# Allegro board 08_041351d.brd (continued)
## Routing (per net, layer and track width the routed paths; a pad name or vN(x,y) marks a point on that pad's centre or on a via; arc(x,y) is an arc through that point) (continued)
IO_L11_SRCC_34_JX4_P: length 94.1
  TOP w0.089: U1.U14 v1(23.54,27.39)
  L12_SIGNAL w0.089: v1(84.38,32.75) 84.25,32.62 83.82,32.62 83.54,32.34 83.54,31.36 84.32,30.59 84.32,29.64 81.28,26.6 81.28,18.47 75.49,12.68 69.12,12.68 68.1,13.7 63.68,13.7 63.17,14.21 58.47,14.21 55.91,11.64 45.47,11.64 44.6,10.78 34.95,10.78 29.87,15.86 24.69,15.86 23.67,16.87 23.67,22.2 23.87,22.39 23.87,27.09 23.57,27.39 v1(23.54,27.39)
  BOTTOM w0.089: v1(84.38,32.75) 84.51,32.62 84.89,32.62 85.24,32.97 JX4.45
IO_L12_MRCC_13_JX2_N: length 53.6
  TOP w0.089: U1.U10 v1(23.54,31.39)
  L12_SIGNAL w0.089: v1(45.52,8.49) 45.26,8.24 45.26,7.47 44.4,6.61 34.7,6.61 30.61,10.7 29.59,10.7 28.88,11.41 28.88,12.5 28.45,12.94 22.28,12.94 21.64,13.57 21.64,14.59 19.99,16.24 19.99,31.2 20.27,31.48 20.75,31.48 20.75,31.48 21,31.72 23.2,31.72 v1(23.54,31.39)
  BOTTOM w0.089: JX2.38 45.53,7.34 45.26,7.6 45.26,8.24 v1(45.52,8.49)
IO_L12_MRCC_13_JX2_P: length 53.6
  TOP w0.089: U1.T9 v1(24.34,32.19)
  L12_SIGNAL w0.089: v1(24.34,32.19) 23.87,31.72 23.87,31.35 23.87,31.25 23.67,31.05 20.95,31.05 20.77,31.22 20.37,31.22 20.25,31.1 20.25,16.34 21.9,14.69 21.9,13.68 22.38,13.19 28.55,13.19 29.14,12.61 29.14,11.52 29.7,10.95 30.71,10.95 34.8,6.86 44.3,6.86 44.96,7.53 44.96,8.42 v1(44.88,8.49)
  BOTTOM w0.089: v1(44.88,8.49) 45.05,8.33 45.05,7.6 44.73,7.28 JX2.36
IO_L12_MRCC_34_JX4_N: length 96.1
  TOP w0.089: v1(23.54,23.39) U1.U19
  L6_SIGNAL w0.089: v1(82.97,32.24) 82.76,32.46 82.01,32.46 81.26,31.71 81.26,22.85 82.98,21.13 82.98,19.82 79.49,16.32 79.49,12.49 79.02,12.02 64.74,12.02 61.34,8.62 61.32,8.62 61.09,8.39 61.09,7.81 59.92,6.64 34.74,6.64 30.72,10.65 29.54,10.65 28.97,11.22 28.97,12.5 25.77,15.7 24.97,15.7 23.93,16.75 23.93,19.92 23.42,20.43 23.42,22.21 23.17,22.46 23.17,22.97 23.54,23.34 v1(23.54,23.39)
  BOTTOM w0.089: v1(82.97,32.24) 82.68,32.53 82.6,32.53 82.24,32.17 JX4.48
IO_L12_MRCC_34_JX4_P: length 96.2
  TOP w0.089: U1.U18 v1(23.54,24.19)
  L6_SIGNAL w0.089: v1(82.98,32.75) 82.98,32.75 82.97,32.75 82.93,32.71 81.9,32.71 81,31.81 81,22.75 82.73,21.02 82.73,19.92 79.24,16.43 79.24,12.6 78.92,12.28 64.63,12.28 61.23,8.87 61.22,8.87 60.84,8.5 60.84,7.92 59.81,6.89 34.84,6.89 30.83,10.9 29.65,10.9 29.23,11.33 29.23,12.61 25.88,15.96 25.08,15.96 24.18,16.85 24.18,20.03 23.67,20.53 23.67,22.21 23.87,22.4 23.87,23.53 23.54,23.86 v1(23.54,24.19)
  BOTTOM w0.089: JX4.46 82.38,32.97 82.6,32.75 v1(82.98,32.75)
IO_L12_MRCC_35_DATA_CLK_N: length 54.2
  TOP w0.127: U17.H11 v1(66.8,33.69) ; U1.K18 v1(29.94,24.19)
  L3_SIGNAL w0.095: v1(29.94,24.19) 29.52,23.77 29.52,22.33 30.96,20.89 40.73,20.89 41.66,19.97 57.7,19.97 v1(59.17,21.44)
  L6_SIGNAL w0.095: v1(66.8,33.69) 66.35,34.14 64.19,34.14 64.06,34.01 64.06,22.46 63.36,21.76 59.49,21.76 v1(59.17,21.44)
IO_L12_MRCC_35_DATA_CLK_P: length 51.1
  TOP w0.127: U1.K17 v1(29.94,24.99) ; U17.G11 v1(66,33.69)
  L7_SIGNAL w0.095: v1(58.73,24.87) 58.73,23.98 54.66,19.92 54.15,19.92 53.34,19.1 45.82,19.1 45.79,19.07 45.5,19.07 45.47,19.1 38.33,19.1 37.26,20.17 36.15,20.17 35.39,20.94 32.69,20.94 31.93,21.7 31.93,24.37 31.65,24.65 31.39,24.65 31.2,24.85 31.2,25.04 30.86,25.38 30.28,25.38 29.94,25.04 v1(29.94,24.99)
  L12_SIGNAL w0.095: v1(58.73,24.87) 59.11,25.25 61.27,25.25 61.66,25.65 61.66,25.83 61.86,26.03 62.04,26.03 62.46,26.45 62.46,26.63 62.66,26.83 62.84,26.83 63.26,27.25 63.26,27.43 63.46,27.63 63.64,27.63 64.06,28.05 64.06,28.23 64.26,28.43 64.44,28.43 64.82,28.81 64.82,30.97 65.2,31.35 65.2,33.26 65.64,33.69 v1(66,33.69)
IO_L13_35_TX_D0_N: length 46.7
  TOP w0.089: U1.H17 v1(31.54,24.99) ; U17.E12 v1(63.6,34.49)
  L7_SIGNAL w0.089: v1(31.54,24.99) 31.54,25.05 31.2,25.38 31.2,25.93 31.4,26.12 31.4,26.12 31.53,26.25 31.67,26.25 32,26.58 32,26.73 32.2,26.92 37.27,26.92 37.47,26.73 37.47,26.42 37.9,25.99 37.9,25.11 39.27,23.73 42.12,23.73 42.29,23.9 43.37,23.9 43.54,23.73 43.99,23.73 44.63,24.37 52.14,24.37 52.57,24.79 52.57,26.19 53.65,27.26 53.65,32.98 55.06,34.4 58.22,34.4 59.23,35.41 62.03,35.41 62.61,34.83 62.94,34.83 63.27,34.49 v1(63.6,34.49)
IO_L13_35_TX_D0_P: length 46.7
  TOP w0.089: U17.D11 v1(62.8,33.69) ; U1.H16 v1(31.54,25.79)
  L7_SIGNAL w0.089: v1(31.54,25.79) 31.69,25.64 31.8,25.64 31.93,25.76 31.93,26.15 32.03,26.25 32.56,26.25 32.71,26.4 32.82,26.4 32.96,26.25 33.31,26.25 33.45,26.4 33.56,26.4 33.71,26.25 34.07,26.25 34.22,26.4 34.33,26.4 34.47,26.25 34.87,26.25 35,26.38 35.23,26.38 35.36,26.25 35.74,26.25 35.74,26.27 35.87,26.4 35.98,26.4 36.12,26.25 36.48,26.25 36.63,26.4 36.74,26.4 36.88,26.25 37.28,26.25 37.64,25.89 37.64,25 39.17,23.48 42.04,23.48 42.29,23.23 43.37,23.23 43.61,23.48 44.1,23.48 44.73,24.11 52.25,24.11 52.82,24.68 52.82,26.08 53.9,27.16 53.9,32.87 55.17,34.14 58.32,34.14 59.34,35.16 61.92,35.16 62.46,34.62 62.46,34.35 62.67,34.15 62.93,34.15 63.02,34.24 63.36,34.24 63.43,34.18 63.43,34 63.19,33.76 62.87,33.76 v1(62.8,33.69)
IO_L13_MRCC_13_JX2_N: length 49.3
  TOP w0.089: U1.Y6 v1(21.14,34.59)
  L15_SIGNAL w0.089: v1(21.14,34.59) 21.41,34.32 21.6,34.32 21.79,34.12 22.07,34.12 22.4,33.8 22.4,33.5 22.58,33.32 22.87,33.32 23.07,33.13 23.07,32.69 23.23,32.52 23.67,32.52 23.93,32.27 23.93,31.92 24.06,31.79 24.4,31.79 24.67,31.53 24.67,31.16 24.8,31.03 28.44,31.03 28.94,30.52 28.94,21.19 30.09,20.05 30.09,18.59 30.44,18.23 30.44,15.04 34.08,11.41 44.14,11.41 45.09,12.36 45.09,13.1 45.56,13.57 46.61,13.57 47.13,13.06 v1(47.42,13.06)
  BOTTOM w0.089: v1(47.42,13.06) 47.42,12.61 47.64,12.39 47.64,12.05 47.93,11.76 JX2.43
IO_L13_MRCC_13_JX2_P: length 49.3
  TOP w0.089: U1.Y7 v1(21.14,33.79)
  L15_SIGNAL w0.089: v1(21.14,33.79) 21.41,34.06 21.5,34.06 21.6,33.96 21.6,33.65 21.8,33.45 22.08,33.45 22.4,33.13 22.4,32.85 22.6,32.65 22.75,32.65 23.07,32.33 23.07,32.02 23.29,31.79 23.7,31.79 23.99,31.5 23.99,31.25 24.27,30.98 24.49,30.98 24.49,30.98 24.69,30.78 28.33,30.78 28.69,30.42 28.69,21.09 29.83,19.94 29.83,18.48 30.19,18.13 30.19,14.94 33.97,11.16 44.25,11.16 45.34,12.25 45.34,13 45.66,13.32 46.5,13.32 46.71,13.11 46.71,12.94 46.54,12.68 46.54,12.55 46.66,12.43 46.79,12.43 v1(47.04,12.68)
  BOTTOM w0.089: v1(47.04,12.68) 47.42,12.3 47.42,12.05 47.13,11.75 JX2.41
IO_L13_MRCC_34_JX4_N: length 83.7
  TOP w0.089: U1.P19 v1(25.94,23.39)
  L13_SIGNAL w0.089: v1(88.52,29.82) 85.03,29.82 83.43,31.41 82.58,31.41 80.9,29.73 80.9,18.52 79.48,17.1 68.05,17.1 67.34,16.39 45.32,16.39 44.4,15.48 40.46,15.48 34.87,21.06 28.73,21.06 27.62,22.17 27.48,22.17 27.2,22.45 27.2,22.89 27.04,23.05 26.6,23.05 26.4,23.25 26.4,23.54 26.31,23.64 26.18,23.64 v1(25.94,23.39)
  BOTTOM w0.089: JX4.53 86.74,29.77 87.03,30.06 88.27,30.06 v1(88.52,29.82)
IO_L13_MRCC_34_JX4_P: length 83.6
  TOP w0.089: U1.N18 v1(26.74,24.19)
  L13_SIGNAL w0.089: v1(26.74,24.19) 26.49,23.94 26.49,23.82 26.58,23.72 26.87,23.72 27.2,23.4 27.2,23.25 27.4,23.05 27.56,23.05 27.87,22.74 27.87,22.28 28.83,21.32 34.98,21.32 40.57,15.73 44.3,15.73 45.21,16.64 67.24,16.64 67.95,17.36 79.38,17.36 80.65,18.62 80.65,29.84 82.48,31.67 83.53,31.67 85.13,30.07 88.06,30.07 v1(88.52,30.53)
  BOTTOM w0.089: JX4.51 86.73,30.57 87.03,30.28 88.27,30.28 v1(88.52,30.53)
IO_L14_35_TX_D1_N: length 41.2
  TOP w0.089: U17.E11 v1(63.6,33.69) ; U1.H18 v1(31.54,24.19)
  L3_SIGNAL w0.089: v1(31.54,24.19) 31.71,24.37 31.84,24.37 31.93,24.45 31.93,26.02 32.11,26.19 37.39,26.19 37.67,26.47 37.67,26.61 37.8,26.74 38.74,26.74 39.32,27.32 39.32,30.47 42.08,33.23 56.76,33.23 57.02,33.5 58.9,33.5 59.69,32.71 59.96,32.71 60.17,32.49 63.06,32.49 63.2,32.63 63.2,33.28 63.6,33.68 v1(63.6,33.69)
IO_L14_35_TX_D1_P: length 41.1
  TOP w0.089: U1.J18 v1(30.74,24.19) ; U17.D10 v1(62.8,32.89)
  L3_SIGNAL w0.089: v1(62.8,32.89) 62.8,33.19 62.69,33.29 60.3,33.29 59.97,32.96 59.79,32.96 59.01,33.75 56.92,33.75 56.65,33.48 41.97,33.48 39.07,30.58 39.07,27.43 38.63,26.99 31.34,26.99 31.14,26.79 31.14,24.6 v1(30.74,24.19)
IO_L14_SRCC_13_JX2_N: length 57.1
  TOP w0.089: U1.Y8 v1(21.14,32.99)
  L12_SIGNAL w0.089: v1(21.14,32.99) 20.01,32.99 19.74,32.71 19.74,31.96 19.23,31.46 19.23,15.73 20.12,14.84 20.12,13.85 22.02,11.94 22.02,11.28 22.7,10.6 28.67,10.6 33.73,5.54 45.75,5.54 47.55,7.35 v1(47.55,8.62)
  BOTTOM w0.089: JX2.44 47.93,7.31 47.64,7.6 47.64,8.07 47.45,8.26 47.45,8.52 v1(47.55,8.62)
IO_L14_SRCC_13_JX2_P: length 57
  TOP w0.089: U1.Y9 v1(21.14,32.19)
  L12_SIGNAL w0.089: v1(21.14,32.19) 20.83,32.49 20.83,32.65 20.74,32.73 20.12,32.73 19.99,32.61 19.99,31.86 19.48,31.35 19.48,15.83 20.37,14.95 20.37,13.95 22.28,12.05 22.28,11.39 22.81,10.86 28.78,10.86 33.84,5.8 45.64,5.8 47.3,7.45 47.3,7.6 47.17,7.73 46.92,7.73 46.79,7.86 46.79,7.98 46.92,8.11 47.17,8.11 47.3,8.24 47.3,8.4 47.21,8.48 47.21,8.48 47.21,8.49 47.17,8.49 v1(47.04,8.62)
  BOTTOM w0.089: JX2.42 47.13,7.31 47.42,7.6 47.42,7.98 47.23,8.17 47.23,8.43 v1(47.04,8.62)
IO_L14_SRCC_34_JX4_N: length 81.1
  TOP w0.089: U1.P20 v1(25.94,22.59)
  L13_SIGNAL w0.089: v1(25.94,22.59) 25.94,20.58 27.48,19.03 31.17,19.03 31.55,18.65 31.55,18.02 32.18,17.38 37.39,17.38 39.9,14.87 44.22,14.87 45.46,13.62 51.81,13.62 52.04,13.39 53.8,13.39 54.36,13.95 58.55,13.95 59.14,14.54 61.39,14.54 62.99,12.94 64.92,12.94 67.69,15.7 76.79,15.7 77.27,16.19 80.19,16.19 82.09,18.09 82.09,29.4 82.48,29.79 83.25,29.79 v1(83.74,30.28)
  BOTTOM w0.089: v1(83.74,30.28) 83.53,30.06 82.56,30.06 82.27,29.77 JX4.54
IO_L14_SRCC_34_JX4_P: length 81.1
  TOP w0.089: U1.N20 v1(26.74,22.59)
  L13_SIGNAL w0.089: v1(83.24,30.78) 83.24,30.49 83.32,30.4 83.32,30.22 83.15,30.04 82.37,30.04 81.84,29.51 81.84,18.19 80.09,16.44 77.17,16.44 76.68,15.96 67.59,15.96 64.82,13.19 63.1,13.19 61.49,14.79 59.03,14.79 58.45,14.21 54.25,14.21 53.69,13.65 52.15,13.65 51.92,13.88 45.57,13.88 44.32,15.12 40.01,15.12 37.5,17.63 32.29,17.63 31.8,18.12 31.8,18.76 31.27,19.29 27.59,19.29 26.19,20.69 26.19,22.23 26.28,22.32 26.47,22.32 v1(26.74,22.59)
  BOTTOM w0.089: JX4.52 82.29,30.57 82.58,30.28 83.29,30.28 83.42,30.41 83.42,30.6 v1(83.24,30.78)
IO_L15_13_JX2_N: length 57.3
  TOP w0.089: U1.W8 v1(21.94,32.99)
  L4_SIGNAL w0.089: v1(21.94,32.99) 21.52,32.57 20.87,32.57 20.73,32.43 20.73,32.18 20.6,32.05 20.09,32.05 19.36,31.32 19.36,20.83 21.16,19.03 25.52,19.03 26.79,17.76 36.78,17.76 38.94,15.6 41.7,15.6 42.47,14.84 42.47,8.49 43.23,7.73 47.86,7.73 48.48,8.35 49.88,8.35 50.22,8.68 v1(50.22,9.38)
  BOTTOM w0.089: v1(50.22,9.38) 50.09,9.51 50.09,9.95 50.33,10.19 JX2.49
IO_L15_13_JX2_P: length 57.3
  TOP w0.089: U1.V8 v1(22.74,32.99)
  L4_SIGNAL w0.089: v1(49.71,9.38) 49.96,9.13 49.96,8.79 49.78,8.6 48.38,8.6 47.75,7.98 43.34,7.98 42.72,8.6 42.72,14.94 41.81,15.86 39.04,15.86 36.88,18.02 26.89,18.02 25.62,19.29 21.26,19.29 19.61,20.94 19.61,31.21 20.19,31.79 22.07,31.79 22.34,32.07 22.34,32.59 v1(22.74,32.99)
  BOTTOM w0.089: JX2.47 49.53,10.26 49.87,9.91 49.87,9.54 v1(49.71,9.38)
IO_L15_34_JX4_N: length 87.5
  TOP w0.089: U1.U20 v1(23.54,22.59)
  L7_SIGNAL w0.089: v1(23.54,22.59) 23.54,16.5 24.18,15.86 26.49,15.86 27.38,14.97 31.24,14.97 32.63,13.57 33.58,13.57 34.47,12.68 34.47,11.92 35.49,10.9 40.44,10.9 40.95,11.41 65.94,11.41 71.28,16.75 73.59,16.75 74.28,17.44 74.28,22.29 74.71,22.71 78.03,22.71 80.32,25 85.47,25 v1(88.61,28.14)
  BOTTOM w0.089: JX4.59 86.74,27.37 87.03,27.66 88.14,27.66 v1(88.61,28.14)
IO_L15_34_JX4_P: length 87.5
  TOP w0.089: U1.T20 v1(24.34,22.59)
  L7_SIGNAL w0.089: v1(24.34,22.59) 24.16,22.41 23.92,22.41 23.79,22.28 23.79,16.61 24.29,16.11 26.6,16.11 27.48,15.22 31.34,15.22 32.74,13.82 33.69,13.82 34.72,12.79 34.72,12.02 35.59,11.16 40.33,11.16 40.84,11.67 65.84,11.67 71.17,17 73.48,17 74.03,17.55 74.03,22.4 74.6,22.97 77.92,22.97 80.21,25.25 85.37,25.25 88.13,28.01 v1(88.13,28.62)
  BOTTOM w0.089: JX4.57 86.75,28.17 87.04,27.88 88.05,27.88 88.23,28.06 88.23,28.24 88.13,28.34 v1(88.13,28.62)
IO_L15_35_TX_D2_N: length 54.5
  TOP w0.089: v1(33.14,22.59) U1.F20 ; U17.E10 v1(63.6,32.89)
  L6_SIGNAL w0.089: v1(33.14,22.59) 32.95,22.4 32.95,21.96 32.68,21.69 32.68,20.53 33.26,19.95 33.26,18.27 33.77,17.76 35.61,17.76 37.01,16.36 39.91,16.36 40.92,15.35 41.37,15.35 42.26,14.46 50.6,14.46 52.19,16.05 52.19,22.71 57.8,28.33 57.8,33.32 58.49,34.02 59.85,34.02 59.86,34.03 62.14,34.03 62.33,33.83 62.33,33.55 62.66,33.23 62.94,33.23 63.13,33.03 63.13,32.75 63.09,32.71 63.09,32.58 63.17,32.49 63.68,32.49 63.81,32.62 63.81,32.68 v1(63.6,32.89)
IO_L15_35_TX_D2_P: length 54.4
  TOP w0.089: U17.D9 v1(62.8,32.09) ; v1(33.14,23.39) U1.F19
  L6_SIGNAL w0.089: v1(33.14,23.39) 32.69,22.94 32.69,22.07 32.42,21.8 32.42,20.42 33.01,19.84 33.01,18.17 33.67,17.51 35.51,17.51 36.9,16.11 39.8,16.11 40.82,15.09 41.26,15.09 42.15,14.21 50.7,14.21 52.44,15.94 52.44,22.61 58.05,28.22 58.05,33.22 58.6,33.76 59.85,33.76 60.26,33.36 62.17,33.36 62.44,33.09 62.44,32.77 62.66,32.56 62.72,32.56 62.91,32.37 62.91,32.21 v1(62.8,32.09)
IO_L16_13_JX2_N: length 49.7
  TOP w0.089: U1.W9 v1(21.94,32.19)
  L15_SIGNAL w0.089: v1(21.94,32.19) 22.3,31.82 22.3,31.21 22.51,31.01 23.79,31.01 24.4,30.4 27.42,30.4 27.93,29.89 27.93,22.27 27.67,22.02 27.67,21.63 28.06,21.25 28.06,20.49 28.69,19.86 28.69,17.89 29.2,17.38 29.2,14.59 29.9,13.89 30.38,13.89 33.62,10.65 48.29,10.65 49.33,9.61 49.33,9.12 49.96,8.48 49.96,8.24 v1(50.22,7.98)
  BOTTOM w0.089: v1(50.22,7.98) 50.09,7.86 50.09,7.6 50.33,7.36 JX2.50
IO_L16_13_JX2_P: length 49.8
  TOP w0.089: U1.W10 v1(21.94,31.39)
  L15_SIGNAL w0.089: v1(49.71,7.98) 49.71,8.38 49.07,9.01 49.07,9.51 48.19,10.4 33.52,10.4 30.28,13.63 29.79,13.63 28.94,14.48 28.94,17.28 28.44,17.78 28.44,19.75 27.8,20.39 27.8,21.15 27.42,21.53 27.42,22.02 27.17,22.27 27.17,30.02 27.04,30.14 24.29,30.14 23.68,30.75 22.05,30.75 21.52,31.29 21.52,31.68 21.63,31.79 21.82,31.79 21.94,31.68 v1(21.94,31.39)
  BOTTOM w0.089: JX2.48 49.53,7.29 49.84,7.6 49.84,7.86 v1(49.71,7.98)
IO_L16_34_JX4_N: length 90
  TOP w0.089: v1(21.94,22.59) U1.W20
  L7_SIGNAL w0.089: v1(21.94,22.59) 21.94,16.07 23.04,14.97 26.21,14.97 27.23,13.95 31.17,13.95 35.1,10.01 40.82,10.01 41.52,10.71 66.39,10.71 68.28,12.61 76.47,12.61 77.63,13.76 80.71,13.76 81.97,15.02 81.97,18.68 81.39,19.26 79.05,19.26 78.6,19.71 78.6,20.67 78.87,20.93 v1(78.87,22.18)
  BOTTOM w0.089: v1(78.87,22.18) 78.64,22.41 78.64,27.16 79.14,27.66 80.48,27.66 80.78,27.37 JX4.60
IO_L16_34_JX4_P: length 90
  TOP w0.089: U1.V20 v1(22.74,22.59)
  L7_SIGNAL w0.089: v1(22.74,22.59) 22.19,22.04 22.19,16.18 23.14,15.22 26.32,15.22 27.34,14.21 31.27,14.21 35.21,10.27 40.71,10.27 41.41,10.97 66.28,10.97 68.18,12.86 76.37,12.86 77.52,14.01 80.6,14.01 81.71,15.12 81.71,18.57 81.28,19.01 78.94,19.01 78.35,19.6 78.35,20.77 78.61,21.04 78.61,21.88 78.51,21.98 78.39,21.98 v1(78.18,22.18)
  BOTTOM w0.089: v1(78.18,22.18) 78.42,22.42 78.42,27.25 79.05,27.88 80.46,27.88 80.76,28.17 JX4.58
IO_L16_35_TX_D3_N: length 52.9
  TOP w0.089: U17.E9 v1(63.6,32.09) ; U1.G18 v1(32.34,24.19)
  L12_SIGNAL w0.089: v1(32.34,24.19) 32.36,24.19 32.69,23.86 32.69,22.46 32.44,22.21 32.44,22.06 33.05,21.44 34.85,21.44 35.7,20.6 35.71,20.59 35.73,20.56 35.74,20.56 37,19.3 37.01,19.29 37.04,19.26 37.06,19.24 38.91,17.38 39.65,17.38 40.67,16.36 43.99,16.36 44.76,17.13 49.4,17.13 50.22,17.94 50.22,24.72 51.89,26.4 56.06,26.4 57.84,28.18 57.84,33.26 58.35,33.76 59.99,33.76 60.26,34.03 61.34,34.03 61.66,33.7 61.66,33.55 61.98,33.23 62.14,33.23 62.46,32.9 62.46,32.75 62.79,32.43 62.94,32.43 62.96,32.41 63.09,32.28 63.13,32.23 63.13,31.9 63.3,31.73 63.43,31.73 63.55,31.86 63.55,32.05 v1(63.6,32.09)
IO_L16_35_TX_D3_P: length 52.9
  TOP w0.089: U17.D8 v1(62.8,31.29) ; U1.G17 v1(32.34,24.99)
  L12_SIGNAL w0.089: v1(32.34,24.99) 32.34,24.66 32,24.33 32,22.39 32.18,22.21 32.18,21.95 32.95,21.19 34.74,21.19 35.53,20.41 35.53,20.4 35.54,20.39 35.55,20.39 36.84,19.1 36.85,19.09 36.85,19.09 36.87,19.07 38.81,17.13 39.55,17.13 40.57,16.11 44.1,16.11 44.86,16.87 49.51,16.87 50.47,17.84 50.47,24.62 52,26.14 56.16,26.14 58.09,28.07 58.09,33.15 58.45,33.51 59.99,33.51 60.14,33.36 61.27,33.36 61.66,32.96 61.66,32.75 61.99,32.43 62.14,32.43 62.46,32.1 62.46,31.95 62.8,31.62 v1(62.8,31.29)
IO_L17_13_JX2_N: length 55.6
  TOP w0.089: U1.U8 v1(23.54,32.99)
  L4_SIGNAL w0.089: v1(52.63,9.38) 52.63,12.81 47.93,17.51 41.49,17.51 41.47,17.53 40.93,17.53 40.91,17.51 38.53,17.51 38.03,18.02 38.03,18.63 37.37,19.29 27.72,19.29 26.19,20.81 22.26,20.81 20.44,22.63 20.44,29.85 20.92,30.33 22.71,30.33 23.36,30.98 23.68,30.98 23.95,31.26 23.95,32.57 v1(23.54,32.99)
  BOTTOM w0.089: JX2.55 52.73,10.17 52.48,9.93 52.48,9.53 v1(52.63,9.38)
IO_L17_13_JX2_P: length 55.7
  TOP w0.089: v1(23.54,32.19) 23.54,32.18 23.93,31.79 U1.U9
  L4_SIGNAL w0.089: v1(52.12,9.38) 51.85,9.65 51.85,9.83 52,9.98 52.25,9.98 52.38,10.1 52.38,12.7 47.83,17.25 41.38,17.25 41.37,17.27 41.03,17.27 41.02,17.25 38.43,17.25 37.77,17.91 37.77,18.52 37.26,19.03 27.61,19.03 26.09,20.56 22.15,20.56 20.18,22.52 20.18,29.95 20.82,30.59 22.61,30.59 23.12,31.1 23.12,32.43 23.24,32.56 23.41,32.56 23.54,32.43 v1(23.54,32.19)
  BOTTOM w0.089: v1(52.12,9.38) 52.25,9.51 52.25,9.89 51.93,10.21 JX2.53
IO_L17_34_JX4_N: length 96.4
  TOP w0.089: U1.Y19 v1(21.14,23.39)
  L7_SIGNAL w0.089: v1(87.86,23.43) 88.29,23.86 88.59,23.86 88.8,23.64 88.8,17.86 84.63,13.7 82.6,13.7 80.67,11.77 69.83,11.77 68.39,10.33 41.92,10.33 40.46,8.87 35.34,8.87 30.64,13.57 29.54,13.57 29.28,13.32 22.66,13.32 22.02,13.95 22.02,14.82 19.61,17.23 19.61,23.7 19.84,23.93 19.99,23.93 20.12,23.81 20.12,23.35 20.25,23.22 20.37,23.22 20.5,23.35 20.5,23.86 20.58,23.93 20.77,23.93 20.86,23.85 20.86,23.66 v1(21.14,23.39)
  BOTTOM w0.089: v1(87.86,23.43) 87.62,23.66 86.98,23.66 86.69,23.37 JX4.69
IO_L17_34_JX4_P: length 96.4
  TOP w0.089: U1.Y18 v1(21.14,24.19)
  L7_SIGNAL w0.089: v1(87.86,24.11) 88.69,24.11 89.05,23.75 89.05,17.76 84.74,13.44 82.71,13.44 80.78,11.51 69.93,11.51 68.5,10.08 42.03,10.08 40.57,8.62 35.23,8.62 30.53,13.32 29.64,13.32 29.39,13.06 22.55,13.06 21.77,13.85 21.77,14.71 19.36,17.13 19.36,23.81 19.74,24.19 v1(21.14,24.19)
  BOTTOM w0.089: v1(87.86,24.11) 87.63,23.88 86.99,23.88 86.7,24.17 JX4.67
IO_L17_35_TX_D4_N: length 54.7
  TOP w0.089: U1.H20 v1(31.54,22.59) ; U17.E8 v1(63.6,31.29)
  L6_SIGNAL w0.089: v1(63.6,31.29) 63.22,31.67 60.3,31.67 59.62,30.99 59.62,26.69 54.98,22.06 54.98,17.63 51.23,13.89 51.23,12.94 50.34,12.05 42.45,12.05 41.43,13.06 40.54,13.06 39.93,13.68 39.93,14.87 39.32,15.48 35.49,15.48 34.22,16.75 33.45,16.75 31.93,18.27 31.93,19.77 31.26,20.44 31.26,22.32 v1(31.54,22.59)
IO_L17_35_TX_D4_P: length 54.8
  TOP w0.089: v1(30.74,22.59) U1.J20 ; U17.D7 v1(62.8,30.49)
  L6_SIGNAL w0.089: v1(30.74,22.59) 31.01,22.32 31.01,20.33 31.68,19.67 31.68,18.16 33.35,16.49 34.11,16.49 35.38,15.22 39.22,15.22 39.68,14.76 39.68,13.57 40.44,12.81 41.33,12.81 42.34,11.79 50.45,11.79 51.49,12.83 51.49,13.78 55.23,17.53 55.23,21.95 59.87,26.59 59.87,30.88 59.94,30.96 62.93,30.96 63.04,30.84 63.04,30.74 v1(62.8,30.49)
IO_L18_13_JX2_N: length 54.7
  TOP w0.089: U1.Y11 v1(21.14,29.79)
  L13_SIGNAL w0.089: v1(52.63,7.98) 52.38,7.73 52.38,7.24 51.24,6.1 33.73,6.1 29.14,10.7 29.14,11.44 27.51,13.06 25.85,13.06 24.71,14.21 23.8,14.21 19.61,18.4 19.61,21.31 19.23,21.69 19.23,28.92 20.01,29.7 20.55,29.7 20.64,29.79 v1(21.14,29.79)
  BOTTOM w0.089: JX2.56 52.73,7.31 52.5,7.54 52.5,7.86 v1(52.63,7.98)
IO_L18_13_JX2_P: length 54.7
  TOP w0.089: U1.W11 v1(21.94,29.79)
  L13_SIGNAL w0.089: v1(21.94,29.79) 21.9,29.83 21.9,29.95 21.77,30.08 21.64,30.08 21.52,29.95 21.52,29.7 21.47,29.66 21.47,29.65 21.27,29.45 20.12,29.45 19.48,28.81 19.48,21.79 19.86,21.41 19.86,18.5 23.91,14.46 24.82,14.46 25.96,13.32 27.62,13.32 29.39,11.54 29.39,10.81 33.84,6.36 51.13,6.36 52.12,7.35 v1(52.12,7.98)
  BOTTOM w0.089: v1(52.12,7.98) 52.25,7.86 52.25,7.6 51.93,7.28 JX2.54
IO_L18_34_JX4_N: length 95.8
  TOP w0.089: U1.W16 v1(21.94,25.79)
  L6_SIGNAL w0.089: v1(83.39,23.2) 83.06,23.2 82.89,23.03 82.89,22.69 85.24,20.34 85.24,14.46 84.61,13.82 82.38,13.82 79.58,11.03 72.67,11.03 68.74,7.09 64.8,7.09 63.53,5.82 33.48,5.82 28.78,10.52 25.85,10.52 25.24,11.12 25.24,13.75 20.66,18.33 20.66,21.35 21.6,22.28 21.6,25.45 v1(21.94,25.79)
  BOTTOM w0.089: JX4.70 82.28,23.37 82.58,23.67 83.07,23.67 83.2,23.54 83.2,23.39 v1(83.39,23.2)
IO_L18_34_JX4_P: length 95.8
  TOP w0.089: U1.V16 v1(22.74,25.79)
  L6_SIGNAL w0.089: v1(83.39,23.89) 82.64,23.14 82.64,22.58 84.99,20.23 84.99,14.56 84.5,14.08 82.27,14.08 79.48,11.28 72.57,11.28 68.63,7.35 64.7,7.35 63.43,6.08 33.58,6.08 28.89,10.78 25.95,10.78 25.5,11.23 25.5,13.86 20.92,18.44 20.92,21.24 21.69,22.02 22.04,22.02 22.34,22.32 22.34,25.67 22.46,25.79 v1(22.74,25.79)
  BOTTOM w0.089: JX4.68 82.3,24.17 82.59,23.89 v1(83.39,23.89)
IO_L18_35_TX_D5_N: length 43
  TOP w0.089: v1(32.34,22.59) U1.G20 ; U17.F8 v1(64.4,31.29)
  L3_SIGNAL w0.089: v1(64.4,31.29) 64.01,30.97 64.01,30.32 63.78,30.09 61.12,30.09 60.43,29.41 58.27,29.41 57.84,29.84 55.95,29.84 55.36,30.42 55.36,31.43 54.8,31.99 54.14,31.99 53.51,31.35 52.53,31.35 51.87,32.01 43.59,32.01 42.97,31.39 41.47,31.39 40.36,30.28 40.36,26.75 38.18,24.57 37.79,24.57 37.79,24.57 34.47,24.57 34.34,24.44 34.34,23.98 34.16,23.81 33.72,23.81 33.71,23.8 33.7,23.8 33.54,23.64 33.54,23.19 33.34,22.99 32.74,22.99 v1(32.34,22.59)
IO_L18_35_TX_D5_P: length 43
  TOP w0.089: U17.E7 v1(63.6,30.49) ; U1.G19 v1(32.34,23.39)
  L3_SIGNAL w0.089: v1(32.34,23.39) 32.08,23.39 31.95,23.52 31.95,23.67 32.09,23.81 33.35,23.81 33.53,23.98 33.53,24.32 33.81,24.59 34.14,24.59 34.32,24.78 34.32,25.12 34.59,25.39 37.47,25.39 37.75,25.12 37.75,24.98 37.9,24.82 38.08,24.82 40.11,26.85 40.11,30.39 41.36,31.64 42.86,31.64 43.49,32.26 51.97,32.26 52.63,31.6 53.4,31.6 54.04,32.24 54.91,32.24 55.61,31.53 55.61,30.53 56.05,30.09 57.94,30.09 58.37,29.66 60.33,29.66 61.01,30.35 61.33,30.35 61.89,30.91 63.49,30.91 63.6,30.8 v1(63.6,30.49)
IO_L19_13_JX2_N: length 56.9
  TOP w0.089: U1.U5 23.93,34.99 v1(23.53,35.39)
  L6_SIGNAL w0.089: v1(55.81,12.36) 55.81,11.03 54.92,10.14 34.87,10.14 30.58,14.43 30.58,14.92 28.88,16.62 28.88,17.72 26.48,20.12 26.48,22.1 26.34,22.24 26.34,23.46 25.95,23.85 25.8,23.85 25.6,24.05 25.6,24.35 25.29,24.65 25,24.65 24.8,24.85 24.8,25.14 24.49,25.45 24.2,25.45 24,25.65 24,25.95 23.69,26.25 23.4,26.25 23.2,26.45 23.2,26.75 22.89,27.05 22.6,27.05 22.4,27.25 22.4,29.93 22.66,30.19 22.66,30.99 22.4,31.25 22.4,33.93 22.6,34.12 22.89,34.12 23.17,34.4 23.17,35.03 v1(23.53,35.39)
  BOTTOM w0.089: JX2.63 55.93,11.67 55.64,11.96 55.64,12.2 v1(55.81,12.36)
IO_L19_13_JX2_P: length 56.9
  TOP w0.089: U1.T5 v1(24.34,35.39)
  L6_SIGNAL w0.089: v1(55.3,12.36) 55.55,12.11 55.55,11.92 55.42,11.79 55.22,11.79 55.09,11.67 55.09,11.54 55.22,11.41 55.42,11.41 55.55,11.28 55.55,11.14 54.81,10.4 34.98,10.4 30.84,14.54 30.84,15.02 29.14,16.72 29.14,17.83 26.74,20.23 26.74,22.04 27.07,22.38 27.07,23.53 26.87,23.72 26.58,23.72 26.34,23.97 26.34,24.26 26.07,24.52 25.78,24.52 25.47,24.83 25.47,25.13 25.28,25.32 24.98,25.32 24.67,25.63 24.67,25.93 24.47,26.12 24.18,26.12 23.87,26.43 23.87,26.73 23.67,26.92 23.38,26.92 23.07,27.23 23.07,30.03 22.91,30.19 22.91,30.99 23.07,31.15 23.07,33.94 23.38,34.25 23.67,34.25 23.86,34.45 23.86,34.74 24.34,35.21 v1(24.34,35.39)
  BOTTOM w0.089: JX2.61 55.13,11.69 55.42,11.98 55.42,12.24 v1(55.3,12.36)
IO_L19_34_JX4_N: length 85.4
  TOP w0.089: U1.R17 v1(25.14,24.99)
  L13_SIGNAL w0.089: v1(25.14,24.99) 25.14,24.66 24.8,24.33 24.8,22.45 25,22.25 25.03,22.25 25.07,22.21 25.07,19.29 26.6,17.76 30.53,17.76 32.31,15.98 37.64,15.98 39.17,14.46 39.17,12.43 40.06,11.54 44.91,11.54 45.29,11.92 54.18,11.92 55.1,12.83 56.67,12.83 58.6,10.9 73.2,10.9 74.22,11.92 81.33,11.92 83.24,13.82 84.25,13.82 85.52,15.09 85.52,21.06 85.93,21.47 87.58,21.47 87.71,21.34 87.71,21.22 v1(87.91,21.01)
  BOTTOM w0.089: JX4.75 86.69,20.97 86.98,21.26 87.66,21.26 v1(87.91,21.01)
IO_L19_34_JX4_P: length 85.5
  TOP w0.089: U1.R16 v1(25.14,25.79)
  L13_SIGNAL w0.089: v1(25.14,25.79) 25.14,25.46 25.47,25.13 25.47,24.85 25.45,24.83 25.45,24.35 25.47,24.33 25.47,22.45 25.33,22.3 25.33,19.39 26.7,18.02 30.64,18.02 32.42,16.24 37.75,16.24 39.42,14.56 39.42,12.53 40.16,11.79 44.81,11.79 45.19,12.17 54.08,12.17 54.99,13.09 56.77,13.09 58.7,11.16 73.1,11.16 74.11,12.17 81.23,12.17 83.13,14.08 84.15,14.08 85.27,15.2 85.27,21.17 85.82,21.72 v1(87.91,21.72)
  BOTTOM w0.089: JX4.73 86.68,21.77 86.97,21.48 87.67,21.48 v1(87.91,21.72)
IO_L19_35_CTRL_OUT0: length 34.9
  TOP w0.127: U17.D4 v1(62.8,27.29) ; U1.H15 v1(31.54,26.59)
  L4_SIGNAL w0.095: v1(31.54,26.59) 31.17,26.96 31.17,27.6 31.36,27.79 40.72,27.79 40.83,27.9 46.49,27.9 47.23,27.16 57.08,27.16 57.84,27.92 59.55,27.92 59.81,27.67 62.16,27.67 62.53,27.29 v1(62.8,27.29)
IO_L19_35_CTRL_OUT1: length 35.6
  TOP w0.127: U17.E6 v1(63.6,28.89) ; v1(32.34,26.59) U1.G15
  L4_SIGNAL w0.095: v1(63.6,28.89) 63.94,28.55 63.94,27.15 63.74,26.95 58.39,26.95 57.77,26.33 46.79,26.33 45.96,27.16 41.9,27.16 41.77,27.03 32.69,27.03 32.34,26.68 v1(32.34,26.59)
IO_L20_13_JX2_N: length 54.7
  TOP w0.089: U1.Y13 v1(21.14,28.19)
  L13_SIGNAL w0.089: v1(55.07,8.41) 55.02,8.35 54.78,8.35 54.39,8.74 51.89,8.74 50.54,7.4 35.06,7.4 33.66,8.8 33.66,9.82 31.47,12 31.47,12.66 30.69,13.44 28.61,13.44 26.95,15.09 24.29,15.09 20.75,18.63 20.75,22.44 20.37,22.82 20.37,28.45 20.66,28.73 20.83,28.73 21.14,28.43 v1(21.14,28.19)
  BOTTOM w0.089: v1(55.07,8.41) 55.07,8.39 55.64,7.82 55.64,7.64 55.93,7.35 JX2.64
IO_L20_13_JX2_P: length 54.7
  TOP w0.089: U1.Y12 v1(21.14,28.99)
  L13_SIGNAL w0.089: v1(54.79,7.98) 54.28,8.49 52,8.49 50.65,7.14 34.95,7.14 33.4,8.69 33.4,9.71 31.22,11.89 31.22,12.55 30.58,13.19 28.5,13.19 26.85,14.84 24.18,14.84 20.5,18.52 20.5,22.33 20.12,22.71 20.12,28.56 20.55,28.99 v1(21.14,28.99)
  BOTTOM w0.089: v1(54.79,7.98) 55.17,7.98 55.42,7.73 55.42,7.6 55.13,7.3 JX2.62
IO_L20_34_JX4_N: length 80.4
  TOP w0.089: U1.R18 v1(25.14,24.19)
  L6_SIGNAL w0.089: v1(80.19,21.19) 80.44,21.44 81.1,21.44 81.22,21.33 81.22,21.2 81.08,21.06 80.7,21.06 80.57,20.94 80.57,20.68 80.7,20.56 80.95,20.56 81.33,20.94 81.61,20.94 81.84,20.7 81.84,20.24 81.27,19.67 78.86,19.67 77.9,18.71 77.9,17.41 76.53,16.03 66.57,16.03 62.69,12.15 60.4,12.15 58.06,9.81 55.4,9.81 54.2,8.62 48.46,8.62 47.46,7.61 36.62,7.61 30.52,13.71 29.82,13.71 27.94,15.59 27.94,16.86 27.29,17.51 26.32,17.51 25.35,18.48 25.35,20.36 25.05,20.66 25.05,21.79 25.54,22.28 25.54,23.53 25.14,23.93 v1(25.14,24.19)
  BOTTOM w0.089: v1(80.19,21.19) 80.29,21.29 80.51,21.29 80.83,20.97 JX4.76
IO_L20_34_JX4_P: length 80.4
  TOP w0.089: U1.T17 v1(24.34,24.99)
  L6_SIGNAL w0.089: v1(24.34,24.99) 24.34,24.72 24.8,24.26 24.8,20.55 25.1,20.25 25.1,18.37 26.21,17.25 27.19,17.25 27.69,16.75 27.69,15.49 29.72,13.46 30.41,13.46 36.51,7.36 47.56,7.36 48.57,8.36 54.31,8.36 55.5,9.56 58.17,9.56 60.5,11.89 62.79,11.89 66.68,15.78 76.64,15.78 78.16,17.3 78.16,18.61 78.96,19.41 81.37,19.41 82.09,20.13 82.09,20.81 81.21,21.7 v1(80.19,21.7)
  BOTTOM w0.089: JX4.74 80.77,21.77 80.51,21.51 80.38,21.51 v1(80.19,21.7)
IO_L20_35_CTRL_OUT2: length 38.7
  TOP w0.127: U1.K14 v1(29.94,27.39) ; U17.E5 v1(63.6,28.09)
  L4_SIGNAL w0.095: v1(63.6,28.09) 63.2,28.49 62.65,28.49 62.41,28.73 62.41,29.08 62.17,29.32 59.14,29.32 58.12,30.33 42.25,30.33 41.3,29.38 29.83,29.38 29.52,29.06 29.52,27.81 v1(29.94,27.39)
IO_L20_35_CTRL_OUT3: length 36.8
  TOP w0.127: U1.J14 v1(30.74,27.39) ; U17.E4 v1(63.6,27.29)
  L4_SIGNAL w0.095: v1(63.6,27.29) 63.22,27.67 62.6,27.67 62.41,27.86 62.41,28.3 62.22,28.49 59.11,28.49 58.85,28.24 57.96,28.24 57.39,28.81 42.09,28.81 41.84,28.56 30.53,28.56 30.34,28.37 30.34,27.78 v1(30.74,27.39)
IO_L21_13_JX2_N: length 57
  TOP w0.089: U1.V10 v1(22.74,31.39)
  L13_SIGNAL w0.089: v1(58.19,8.87) 58.07,9 58.07,9.51 57.18,10.4 34.5,10.4 32.51,12.38 32.51,12.71 31.02,14.21 29.37,14.21 27.72,15.86 24.56,15.86 22.4,18.02 22.4,20.28 22.02,20.66 22.02,22.08 22.27,22.33 22.27,28.2 22.6,28.52 22.75,28.52 23.07,28.84 23.07,31.05 v1(22.74,31.39)
  BOTTOM w0.089: v1(58.19,8.87) 58.33,9.01 JX2.69
IO_L21_13_JX2_P: length 57.1
  TOP w0.089: U1.V11 v1(22.74,29.79)
  L13_SIGNAL w0.089: v1(22.74,29.79) 22.79,29.84 22.79,30.46 22.66,30.59 22.53,30.59 22.4,30.46 22.4,28.98 21.95,28.52 21.8,28.52 21.6,28.33 21.6,22.25 21.77,22.08 21.77,20.56 22.15,20.17 22.15,17.91 24.46,15.6 27.61,15.6 29.26,13.95 30.91,13.95 32.26,12.61 32.26,12.28 34.39,10.14 57.08,10.14 57.81,9.4 57.81,9 v1(57.68,8.87)
  BOTTOM w0.089: v1(57.68,8.87) 57.53,9.03 JX2.67
IO_L21_34_JX4_N: length 85.6
  TOP w0.089: U1.V18 v1(22.74,24.19)
  L13_SIGNAL w0.089: v1(87.92,19.42) 87.46,19.87 86.8,19.87 86.41,19.48 86.41,14.97 83.87,12.43 83.87,11.92 83.11,11.16 74.6,11.16 73.59,10.14 58.22,10.14 57.46,10.9 35.66,10.9 34.8,11.77 34.8,13.32 33.81,14.31 31.7,14.31 30.53,15.48 28.75,15.48 27.23,17 25.85,17 25.09,17.76 24.33,17.76 23.42,18.67 23.42,22.03 23.17,22.28 23.17,24.45 23.02,24.59 22.86,24.59 22.74,24.47 v1(22.74,24.19)
  BOTTOM w0.089: v1(87.92,19.42) 87.67,19.66 86.98,19.66 86.69,19.37 JX4.79
IO_L21_34_JX4_P: length 85.5
  TOP w0.089: U1.V17 v1(22.74,24.99)
  L13_SIGNAL w0.089: v1(87.92,20.13) 86.7,20.13 86.16,19.59 86.16,15.07 83.62,12.53 83.62,12.02 83,11.41 74.5,11.41 73.48,10.4 58.32,10.4 57.56,11.16 35.77,11.16 35.05,11.87 35.05,13.42 33.91,14.56 31.81,14.56 30.64,15.73 28.86,15.73 27.34,17.25 25.96,17.25 25.2,18.02 24.44,18.02 23.67,18.78 23.67,22.08 23.93,22.33 23.93,24.31 23.65,24.58 23.42,24.58 23.01,24.99 v1(22.74,24.99)
  BOTTOM w0.089: JX4.77 86.73,20.17 87.02,19.88 87.67,19.88 v1(87.92,20.13)
IO_L21_35_CTRL_OUT4: length 52.8
  TOP w0.127: U17.F6 v1(64.4,28.89) ; U1.N15 v1(26.74,26.59)
  L13_SIGNAL w0.095: v1(26.74,26.59) 26.79,26.59 27.23,26.14 29.1,26.14 29.79,25.45 30.21,25.45 30.28,25.38 30.33,25.33 36.48,25.33 36.67,25.13 36.67,24.85 36.99,24.53 37.28,24.53 37.47,24.33 37.47,23.96 38.25,23.19 38.25,23.13 39.42,21.95 41.58,21.95 41.96,21.57 48.95,21.57 51.61,24.24 51.61,29.95 52.5,30.84 52.5,32.24 53.27,33 57.89,33 58.58,32.32 58.86,32.32 59.19,31.99 60.02,31.99 60.26,31.75 62.89,31.75 63.26,31.39 63.26,31.15 63.46,30.95 63.7,30.95 64.06,30.59 64.06,29.23 v1(64.4,28.89)
IO_L21_35_CTRL_OUT5: length 52
  TOP w0.127: U1.N16 v1(26.74,25.79) ; U17.F5 v1(64.4,28.09)
  L3_SIGNAL w0.095: v1(60.25,35.8) 55.3,35.8 54.83,35.33 50.87,35.33 50.31,35.9 47.5,35.9 47.16,35.55 44.63,35.55 44.22,35.15 42.34,35.15 38.33,31.13 38.33,28.65 37.48,27.79 30.66,27.79 30.4,27.53 30.4,27.25 30.08,26.93 29.79,26.93 29.12,26.25 27.21,26.25 26.75,25.79 v1(26.74,25.79)
  L4_SIGNAL w0.095: v1(64.4,28.09) 64.4,28.41 64,28.81 64,34.91 63.74,35.16 60.89,35.16 v1(60.25,35.8)
IO_L22_34_JX4_N: length 74.9
  TOP w0.089: U1.W19 v1(21.94,23.39)
  L3_SIGNAL w0.089: v1(72.48,13.41) 72.15,13.41 71.87,13.13 68.91,13.13 65.61,16.43 56.99,16.43 55.89,15.33 35.55,15.33 34.39,14.17 31.54,14.17 30.71,15.01 24.62,15.01 22.08,17.55 22.08,21.85 21.54,22.39 21.54,22.99 v1(21.94,23.39)
  BOTTOM w0.089: v1(72.48,13.41) 72.48,13.8 73.2,14.52 73.2,15.79 74.35,16.94 79.3,16.94 79.81,17.44 79.81,19.41 80.06,19.67 80.49,19.67 80.79,19.37 JX4.80
IO_L22_34_JX4_P: length 75
  TOP w0.089: U1.W18 v1(21.94,24.19)
  L3_SIGNAL w0.089: v1(21.94,24.19) 22.33,23.79 22.33,17.65 24.73,15.26 30.81,15.26 31.65,14.42 34.29,14.42 35.45,15.58 55.78,15.58 56.88,16.68 65.71,16.68 69.01,13.38 71.76,13.38 71.97,13.59 v1(71.97,13.91)
  BOTTOM w0.089: JX4.78 80.77,20.17 80.48,19.88 79.97,19.88 79.59,19.5 79.59,17.53 79.21,17.15 74.26,17.15 72.99,15.88 72.99,14.61 72.29,13.91 v1(71.97,13.91)
IO_L22_35_CTRL_OUT6: length 54.1
  TOP w0.127: U17.F4 v1(64.4,27.29) ; U1.L14 v1(28.34,27.39)
  L13_SIGNAL w0.095: v1(64.4,27.29) 64.82,27.72 64.82,31.48 64.57,31.73 63.55,31.73 63.53,31.75 63.46,31.75 63.26,31.95 63.26,32.11 62.94,32.43 60.06,32.43 59.11,33.38 52.5,33.38 51.36,32.24 51.36,25.76 49.5,23.9 49.49,23.9 49.29,23.71 49.29,23.55 48.97,23.23 47.68,23.23 47.13,22.67 46.52,22.67 46.18,22.33 39.8,22.33 37.47,24.66 37.47,25.13 37.28,25.33 36.99,25.33 36.67,25.65 36.67,25.93 36.48,26.13 30.42,26.13 30.27,26.27 30.27,26.73 30.08,26.93 29.37,26.93 28.91,27.39 v1(28.34,27.39)
IO_L22_35_CTRL_OUT7: length 49.2
  TOP w0.127: U1.L15 v1(28.34,26.59) ; U17.G4 v1(66,27.29)
  L4_SIGNAL w0.095: v1(28.34,26.59) 28.69,26.59 29.39,25.89 29.39,22.59 30.09,21.89 37.96,21.89 38.72,21.13 41.14,21.13 41.58,21.57 50.15,21.57 51.8,19.92 61.2,19.92 62.76,21.48 63.46,21.48 66.41,24.43 66.41,26.88 v1(66,27.29)
IO_L23_34_CTRL_IN0: length 40.5
  TOP w0.127: U1.N17 v1(26.74,24.99)
  TOP w0.14: U22.13 55.39,30.13 55.2,29.94 v1(54.28,29.94)
  L13_SIGNAL w0.095: v1(26.74,24.99) 27.06,24.99 27.52,24.53 28.48,24.53 28.67,24.33 28.67,24.06 29.81,22.93 36.48,22.93 36.8,22.61 36.8,22.45 36.99,22.25 37.09,22.25 40.18,19.16 45.42,19.16 45.5,19.07 45.79,19.07 45.87,19.16 49.07,19.16 49.29,19.37 49.29,19.73 49.49,19.93 49.85,19.93 52.88,22.97 52.88,26.27 53.65,27.03 53.65,29.67 53.91,29.94 v1(54.28,29.94)
IO_L23_34_CTRL_IN1: length 44.1
  TOP w0.127: U1.P18 v1(25.94,24.19)
  TOP w0.14: v1(54.28,30.72) 54.54,30.98 U22.12
  L13_SIGNAL w0.095: v1(25.94,24.19) 25.94,24.21 26.37,24.65 26.82,24.65 27.2,24.27 27.2,24.05 27.39,23.85 27.62,23.85 28,23.47 28,23.25 28.19,23.05 28.42,23.05 29.26,22.21 35.74,22.21 37.26,20.68 38,20.68 38.75,19.93 38.75,18.95 39.42,18.27 40.66,18.27 40.82,18.43 49.77,18.43 49.97,18.63 49.97,18.91 53.9,22.84 53.9,29.39 54.07,29.56 54.5,29.56 54.66,29.72 54.66,30.33 v1(54.28,30.72)
IO_L23_35_SPI_CLK: length 57.2
  TOP w0.127: U17.J5 v1(67.6,28.09) ; U1.M15 v1(27.54,26.59)
  L13_SIGNAL w0.095: v1(27.54,26.59) 27.54,26.91 27.87,27.25 27.87,27.42 28.25,27.79 30.01,27.79 30.27,27.53 30.27,27.29 30.64,26.93 36.61,26.93 36.8,26.74 36.8,26.45 36.99,26.25 37.28,26.25 38.15,25.38 38.15,25.13 39.93,23.35 42.16,23.35 42.29,23.23 42.72,23.23 42.79,23.16 47.11,23.16 48.19,24.24 49.2,24.24 51.11,26.14 51.11,32.62 52.25,33.76 59.85,33.76 60.26,33.35 62.94,33.35 63.26,33.03 63.26,32.75 63.46,32.55 66.82,32.55 67.14,32.23 67.14,29.29 67.24,29.19 67.24,28.77 67.36,28.65 67.36,28.33 v1(67.6,28.09)
IO_L23_35_SPI_ENB: length 55.8
  TOP w0.127: U17.K6 v1(68.4,28.89) ; U1.M14 v1(27.54,27.39)
  L4_SIGNAL w0.095: v1(60.69,18.52) 60.44,18.27 52.63,18.27 50.15,20.75 47.74,20.75 47.49,20.49 45.39,20.49 45.14,20.75 38.22,20.75 37.39,21.57 29.83,21.57 29.01,22.4 29.01,25.64 28.5,26.14 28.25,26.14 28,26.39 28,26.61 27.54,27.07 v1(27.54,27.39)
  L12_SIGNAL w0.095: v1(68.4,28.89) 68,28.49 65.52,28.49 65.14,28.11 65.14,23.35 64.31,22.52 64,22.52 61.01,19.54 61.01,18.84 v1(60.69,18.52)
IO_L24_34_CTRL_IN2: length 60.8
  TOP w0.127: U1.P15 v1(25.94,26.59)
  TOP w0.14: U22.11 v1(54.52,31.48)
  L12_SIGNAL w0.095: v1(54.03,12.94) 51.54,12.94 51.16,12.55 47.68,12.55 47.42,12.3 44.4,12.3 43.77,11.67 35.61,11.67 33.33,13.95 32.44,13.95 30.02,16.36 29.52,16.36 26.6,19.29 26.6,20.05 26.34,20.3 26.34,26.02 25.94,26.42 v1(25.94,26.59)
  L16_SIGNAL w0.095: v1(54.52,31.48) 54.14,31.48 53.9,31.24 53.9,24.37 52.38,22.84 52.38,13.95 53.39,12.94 v1(54.03,12.94)
IO_L24_34_CTRL_IN3: length 43.7
  TOP w0.127: U1.P16 v1(25.94,25.79)
  TOP w0.14: U22.10 54.75,31.98 54.18,32.54 54.18,36.61 v1(54.54,36.96)
  L3_SIGNAL w0.095: v1(54.54,36.96) 53.66,36.09 52.35,36.09 51.73,36.71 46.06,36.71 45.79,36.98 44.93,36.98 44.39,37.52 42.74,37.52 40.34,35.12 40.34,33.69 37.87,31.22 37.87,29.02 37.4,28.56 30.53,28.56 30.34,28.37 30.34,27.99 30.15,27.79 29.77,27.79 28.9,26.93 26.49,26.93 26.33,26.77 26.33,26.18 v1(25.94,25.79)
IO_L24_35_SPI_DI: length 47.3
  TOP w0.127: U17.J4 v1(67.6,27.29) ; U1.K16 v1(29.94,25.79)
  L4_SIGNAL w0.095: v1(29.94,25.79) 30,25.79 30.28,25.51 30.28,22.46 30.53,22.21 38.38,22.21 38.58,22 41.31,22 41.71,22.4 46.02,22.4 46.34,22.71 47.17,22.71 47.49,22.4 59.16,22.4 59.73,21.83 63.22,21.83 64.49,23.1 64.49,23.65 65.27,24.43 65.27,25.38 65.65,25.76 65.65,27.53 65.79,27.67 67.22,27.67 v1(67.6,27.29)
IO_L24_35_SPI_DO: length 48.5
  TOP w0.127: U1.J16 v1(30.74,25.79) ; U17.L6 v1(69.2,28.89)
  L3_SIGNAL w0.095: v1(30.74,25.79) 30.34,25.39 30.34,22.21 31.32,21.23 41.29,21.23 41.76,20.76 45.28,20.76 45.4,20.63 47.32,20.63 47.45,20.76 50.17,20.76 50.47,21.06 57.33,21.06 59.74,23.48 63.04,23.48 63.94,24.37 63.94,25.13 64.16,25.35 64.54,25.35 65.66,26.48 65.66,26.63 65.98,26.95 66.14,26.95 66.46,27.27 66.46,27.43 66.78,27.75 66.94,27.75 67.26,28.07 67.26,28.23 67.58,28.55 68.54,28.55 68.88,28.89 v1(69.2,28.89)
J3-9: length 103.4
  TOP w0.14: J3.9 15.95,25.83 15.82,25.95 v1(14.53,25.95) ; U5.7 78.48,58.66 78.67,58.84 v1(78.67,59.43)
  L7_SIGNAL w0.095: v1(78.67,59.43) 77.79,60.31 73.59,60.31 68.76,55.48 64.57,55.48 60.12,51.04 42.6,51.04 38.66,47.1 36.88,47.1 34.6,44.81 32.06,44.81 31.55,44.3 27.87,44.3 27.48,43.92 21.52,43.92 15.93,38.34 15.93,27.35 v1(14.53,25.95)
  L15_SIGNAL w0.095: v1(1.83,28.3) 3.74,26.4 7.55,26.4 7.99,25.95 v1(14.53,25.95)
  BOTTOM w0.14: 3.1,28.3 3.08,28.32 1.85,28.32 v1(1.83,28.3)
JTAG_TCK: length 26.7
  TOP w0.127: U1.F9 v1(33.14,32.19)
  L6_SIGNAL w0.095: v1(31.34,54.08) 31.34,52.39 33.07,50.65 33.07,48.85 32.99,48.76 32.99,48.48 33.07,48.4 33.07,41.51 31.17,39.61 31.17,33.68 31.39,33.45 31.68,33.45 32,33.13 32,32.85 32.19,32.65 32.67,32.65 v1(33.14,32.19)
  BOTTOM w0.14: JX1.1 31.13,54.29 v1(31.34,54.08)
JTAG_TDI: length 17.8
  TOP w0.127: U1.G6 v1(32.34,34.59)
  L3_SIGNAL w0.095: v1(32.34,34.59) 32.34,34.63 31.93,35.03 31.93,40.49 32.69,41.26 32.69,47.48 31.93,48.24 31.93,49.51 v1(31.93,49.51)
  BOTTOM w0.14: JX1.4 v1(31.93,49.51)
JTAG_TDO: length 24
  TOP w0.127: U1.F6 v1(33.14,34.59)
  L6_SIGNAL w0.095: v1(31.93,54.08) 31.68,53.83 31.68,52.81 33.45,51.04 33.45,50.12 33.79,49.78 33.79,48.61 33.45,48.27 33.45,41 31.87,39.42 31.87,35.37 32.19,35.05 32.35,35.05 32.82,34.59 v1(33.14,34.59)
  BOTTOM w0.14: JX1.3 v1(31.93,54.08)
JTAG_TMS: length 18
  TOP w0.127: U1.J6 v1(30.74,34.59)
  L3_SIGNAL w0.095: v1(31.13,49.55) 31.17,49.51 31.17,46.08 29.78,44.7 29.78,41.1 30.33,40.56 30.33,34.98 30.72,34.59 v1(30.74,34.59)
  BOTTOM w0.14: JX1.2 v1(31.13,49.55)
JX3_SD1_CDN: length 100.6
  TOP w0.14: U5.9 77.25,57.91 v1(76.89,58.27)
  L12_SIGNAL w0.095: v1(76.89,58.27) 74.73,58.27 72.7,60.31 66.25,60.31 66.2,60.36 65.73,60.36 65.68,60.31 58.22,60.31 54.03,56.12 30.53,56.12 28.88,57.77 20.63,57.77 16.56,53.7 15.17,53.7 5.89,44.43 5.89,41 4.75,39.86 4.75,29.95 5.26,29.45 5.26,28.43 6.32,27.37 v1(6.83,27.37)
  BOTTOM w0.14: JX3.41 v1(6.83,27.37)
JX_VCCO_13: length 111.2
  TOP w0.127: U1.Y10 v1(21.14,31.39) ; U1.U11 v1(23.54,29.79) ; U1.W7 v1(21.94,33.79) ; U1.T8 v1(24.34,32.99)
  L3_SIGNAL w0.406: v1(2.47,17.13) 2.47,20.17 3.35,21.06 3.99,21.06 v1(5.01,22.08)
  BOTTOM w0.254: C169.1 20.05,32.56 20.05,31.29 C170.1
  BOTTOM w0.305: v1(5.39,22.46) v1(5.01,22.08) 4.96,22.04 U21.1 4.96,20.15 5.2,19.92 5.2,19.6 R58.1
  BOTTOM w0.406: C170.1 20.12,30.72 20.12,29.76 20.37,29.51 20.37,21.57 19.61,20.81 19.61,18.14 20.25,17.51 23.17,17.51 23.41,17.75 24.47,17.75 24.5,17.77 24.88,17.77 24.91,17.75 25.72,17.75 25.96,17.51 35.66,17.51 35.82,17.66 38.2,17.66 40.13,15.73 52.5,15.73 56.19,19.41 58.75,19.41 59.18,18.98 59.18,18.26 59.49,17.95 60.06,17.95 60.07,17.94 64.81,17.94 66.03,19.16 68.76,19.16 69.39,18.52 69.39,14.08 71.17,12.3 71.17,9.76 69.53,8.12 JX2.98 ; C170.1 20.88,30.46 22.86,30.46 v1(23.54,29.79) 24.06,30.31 C48.1 ; C170.1 20.37,31.03 20.73,31.39 v1(21.14,31.39) ; v1(20.25,40.88) C27.1 v1(18.85,39.61) ; R57.1 v1(2.47,17.13) ; C46.1 v1(18.85,28.05) ; C167.1 v1(18.85,26.52) ; C171.1 v1(18.85,34.14) ; C243.2 v1(6.28,21.7)
  BOTTOM w0.508: JX3.45 v1(9.54,28.97) JX3.46
  vias: v1(19.61,39.61)
JX_VCCO_34: length 17.2
  TOP w0.127: U1.W17 v1(21.94,24.99) ; U1.N19 v1(26.74,23.39) ; U1.T18 v1(24.34,24.19) ; U1.V14 v1(22.74,27.39) ; U1.Y20 v1(21.14,22.59) ; U1.R15 v1(25.14,26.59)
  TOP w0.254: U22.14 56.44,29.45 v1(56.19,29.19) ; C246.1 v1(55.11,29.25)
  TOP w0.406: v1(57.08,22.97) C2.1 v1(54.41,22.97)
  BOTTOM w0.406: C4.1 v1(26.09,19.79) ; C22.1 v1(18.85,24.87) ; C3.1 v1(23.04,19.79) ; C15.1 v1(21.52,19.79) ; v2(61.53,7.47) JX2.78 ; JX2.80 v2(62.33,7.47) 62.33,7.56 61.65,8.24 v2(61.52,8.24) 62.33,9.04 JX2.79 ; C7.1 v1(24.56,19.79) ; C18.1 v1(18.85,23.48)
JX_VIN: length 23.8
  TOP w0.305: R56.1 v1(28.25,55.73) ; 70.03,6.33 69.93,6.43 69.43,6.43
  TOP w0.406: R23.1 v2(70.03,0.87) ; C36.1 v1(40.6,57.09)
  BOTTOM w0.406: v1(31.68,5.06) v1(31.17,5.06) ; JX1.57 v1(53.53,54.09) v2(53.53,53.46) ; v2(71.73,5.82) 72.32,5.82 73.08,5.06 73.08,4.62 R25.2 ; JX1.59 v1(54.33,54.08) 54.41,54.08 v2(54.79,53.7)
  BOTTOM w0.508: v1(53.53,5.19) JX2.58 ; v1(53.53,5.19) 53.65,5.06 54.03,5.06 54.28,5.32 54.33,5.32 JX2.60 ; v1(53.53,5.19) v1(53.53,4.56) ; v2(54.54,49.64) 54.36,49.81 54.33,49.81 ; JX1.58 53.53,49.76 ; 53.53,49.76 53.27,49.76 53.15,49.64 v2(53.14,49.64) ; 53.53,49.76 v2(53.9,49.38) 54.33,49.81 ; 54.33,49.81 JX1.60 ; JX2.59 54.33,9.81 v2(54.15,9.63) v2(53.52,9.63) 53.53,9.64 JX2.57 ; v1(35.36,4.17) v1(35.36,4.68) 35.36,5.23 35.13,5.47 JX2.12
  vias: v1(39.93,57.13) v1(40.31,57.64) v1(53.14,4.17) v2(62.92,8.11) v2(63.55,8.11) v2(64.19,8.11) v2(70.79,7.98) v2(71.05,5.44) v2(71.43,7.73)
PG_1P0V: length 3
  TOP w0.305: v1(27.87,6.84) 27.67,6.65 R304.1 ; v1(24.26,4.17) 23.89,4.17 23.76,4.3 U18.16 ; v2(62.66,4.68) 62.96,4.98 U4.28
PG_1P8V: length 133.6
  TOP w0.305: U4.29 63.86,4.48 63.81,4.43 v2(63.49,4.43) ; U9.5 41.06,52.44 41.33,52.18 42.72,52.18 v2(43.11,52.56) ; v2(70.41,4.93) 70.36,4.98 U4.13
  TOP w0.406: v2(43.36,53.19) 43.36,52.81 v2(43.11,52.56)
  L4_SIGNAL w0.406: v2(73.46,13.46) 73.46,12.55 69.78,8.87 69.78,6.9 70.41,6.27 v2(70.41,4.93) 69.65,4.93 68.57,6.01 65.39,6.01 64.7,5.32 64.7,4.74 64.38,4.43 v2(63.49,4.43) 63.49,5.44 62.85,6.08 58.47,6.08 55.3,2.9 46.79,2.9 42.72,6.97 36.5,6.97 v1(34.47,4.93)
  L12_SIGNAL w0.406: v2(73.46,13.46) 73.46,15.35 74.16,16.05 74.16,23.35 74.92,24.11 74.92,27.16 77.33,29.57 77.33,30.4 76.82,30.91 76.82,32.51 70.92,38.41 70.92,42.27 71.55,42.91 71.55,49.13 69.65,51.04 43.74,51.04 43.11,51.67 v2(43.11,52.56) 43.11,52.94 v2(43.36,53.19)
  BOTTOM w0.406: R25.1 72.06,4.55 71.73,4.88 70.81,4.88 70.77,4.93 v2(70.41,4.93)
  BOTTOM w0.508: JX2.10 34.33,5.08 v1(34.47,4.93)
PG_MODULE: length 120.2
  TOP w0.14: Q14.1 v1(30.51,50.68) ; R43.2 30.66,11.79 v1(30.41,12.05)
  L3_SIGNAL w0.095: v1(30.41,12.05) 29.41,13.04 21.67,13.04 19.86,14.84 19.86,38.34 21.52,39.99 21.52,42.15 25.58,46.21 26.27,46.21 27.99,47.93 27.99,49.13 29.52,50.65 30.48,50.65 v1(30.51,50.68) 37.68,50.68 39.83,48.54 41.85,48.54 42.06,48.75 49.46,48.75 49.84,48.37 54.66,48.37 58.22,51.92 58.22,56.88 60.12,58.78 71.5,58.78 72.26,58.02 v1(72.95,58.02)
  L4_SIGNAL w0.095: v1(35.61,12.43) 35.23,12.05 v1(30.41,12.05)
  BOTTOM w0.14: v1(35.61,12.43) 35.36,12.43 35.13,12.2 JX2.11 ; v1(72.95,58.02) 73.2,57.77 76.25,57.77 76.38,57.89 77.14,57.89 77.39,58.14 U6.7
PHY1_1V8: length 14.8
  TOP w0.305: v1(27.25,7.21) 27.36,7.21 27.73,7.34 v1(27.74,7.35)
  TOP w0.381: v1(26.98,3.28) 28.44,3.28
  TOP w0.406: v2(15.13,0.83) 15.13,1.38 15,1.51 ; v1(29.26,2.01) 29.26,2.65 28.94,2.97 E14.2 28.69,2.97 28.37,2.65 v1(28.37,2.01)
  TOP w0.508: 28.44,3.28 E14.2
  BOTTOM w0.305: U10.11 19.89,2.24 20.12,2.01 ; v1(27.25,7.21) 27.12,7.34 U10.49 25.59,7.35 24.94,7.35 24.69,7.09 24.69,6.08 24.92,5.84 U10.52 ; U10.10 20.39,2.29 20.12,2.01 ; 20.12,2.01 v1(20.12,1.63)
  BOTTOM w0.508: v1(26.98,3.28) 27.36,2.9 C212.1 ; R11.1 v1(29.77,4.05)
  vias: v1(19.61,1.63)
PHY1_AVDD_1V8: length 20.4
  TOP w0.305: v1(22.89,11.81) 22.28,12.43 C218.1 C201.1
  TOP w0.508: C203.1 18.47,11.03 v1(19.23,11.79) C211.1
  BOTTOM w0.254: v1(16.18,9.89) 16.32,9.89 17.39,9.34 U10.26 ; U10.3 23.89,3.57 23.42,4.05
  BOTTOM w0.305: v1(21.26,11.79) 21.39,11.66 U10.35 ; 23.42,4.05 20.63,4.05 20.25,4.43 v2(19.86,4.43) 19.36,4.43 18.91,4.87 18.91,5.38 18.45,5.84 U10.19 ; U10.38 v1(22.89,11.81)
  BOTTOM w0.406: v2(15.8,11.54) 15.67,11.54 15.04,12.17 15.04,12.72 C219.1 ; C210.1 24.25,16.52 24.25,16.77 v2(24.69,17.22) ; 23.93,14.46 23.09,14.46 v1(23.04,14.41)
PHY1_AVDD_1V8_OUT: length 107.5
  L15_SIGNAL w0.406: v2(36.63,4.3) 35.61,3.28 34.22,3.28 33.45,4.05 31.55,4.05 31.04,3.54 28.88,3.54 27.23,5.19 26.09,5.19 25.58,5.7 25.58,8.36 25.07,8.87 24.69,8.87 v1(23.67,9.89) 23.67,10.52 24.4,11.25 24.4,12.27 24.32,12.35 24.32,12.76 24.61,13.05 24.74,13.05 25.58,13.89 25.58,13.95 26.04,14.41 v1(26.09,14.41)
  L16_SIGNAL w0.406: v2(36.63,4.3) 37.52,3.41 52.5,3.41 53.07,2.84 55.36,2.84 59.74,7.22 59.74,9 62.41,11.67 62.41,15.98 57.46,20.94 57.46,22.21 57.96,22.71 57.96,27.54 56.82,28.68 56.82,29.83 57.71,30.72 57.71,33.26 59.11,34.65 59.11,35.8 60.25,36.94 64.42,36.94 65.46,37.98 65.46,41.51 67.87,43.92 73.08,43.92 v1(73.71,43.29)
  BOTTOM w0.305: U10.39 23.39,10.3 23.67,10.01 v1(23.67,9.89) ; U24.5 75.13,42.48 74.98,42.33 74.67,42.33 v1(73.71,43.29)
  BOTTOM w0.406: R3.2 26.04,14.46 v1(26.09,14.41)
PHY1_AVDD_3V3: length 9.8
  TOP w0.381: C208.1 v1(16.44,9.25)
  TOP w0.406: C49.1 v1(18.47,12.55) ; E15.2 v1(14.72,19.09) v1(14.72,19.86)
  TOP w0.508: C217.1 v1(24.82,12.55)
  BOTTOM w0.254: v1(16.44,9.25) 17.25,8.84 U10.25
  BOTTOM w0.305: v1(16.44,9.25) 16.18,9.25 15.8,8.87 C214.1 16.93,6.34 U10.20
PHY1_DVDD_1V0: length 28.2
  TOP w0.508: v1(26.21,12.55) C63.1 28.67,12.55 C58.1 ; C73.1 23.8,11.79 v1(23.89,11.7)
  L6_SIGNAL w0.381: v1(24.89,11.74) 23.93,11.74 v1(23.89,11.7)
  L6_SIGNAL w0.406: v1(23.89,11.7) 23.89,11.22 25.07,10.04 25.07,9.63 25.45,9.25 25.45,2.9 26.34,2.01 v2(27.36,2.01)
  L16_SIGNAL w0.406: v2(27.36,2.01) 25.96,2.01 25.04,1.09 22.4,1.09 22.02,1.47 v2(22.02,1.76)
  BOTTOM w0.254: v2(22.02,1.76) 22.02,1.89 22.39,2.26 U10.6
  BOTTOM w0.305: U10.42 v1(24.89,11.74) ; U10.40 v1(23.89,11.7)
  BOTTOM w0.406: C75.1 v2(27.36,2.01)
  BOTTOM w0.508: v1(24.89,11.74) 25.71,12.55 v1(26.21,12.55)
PHY1_LED_0: length 69.8
  TOP w0.508: R14.1 v1(13.64,56.5) 12.9,56.5 Q2.1
  L12_SIGNAL w0.102: v1(17.32,2.9) 15.29,2.9 13.9,4.3 11.48,4.3 8.18,7.6 8.18,10.9 6.15,12.94 6.15,15.35 3.74,17.76 3.74,22.84 3.1,23.48 3.1,38.84 5.39,41.13 5.39,45.96 13.64,54.21 v1(13.64,56.5)
  BOTTOM w0.254: v1(17.32,2.9) 17.45,2.9 17.69,3.14 U10.14
PHY1_LED_1: length 23.4
  TOP w0.508: Q1.1 33.43,9.63 v1(32.82,9.63) 32.63,9.63 32.25,10.01 R13.1
  L4_SIGNAL w0.406: v1(20.12,3.85) 19.29,3.85 18.98,4.17 18.98,5.7 21.45,8.17 23.86,8.17 26.6,10.9 31.55,10.9 v1(32.82,9.63)
  BOTTOM w0.254: v1(20.12,3.85) 19.08,3.85 18.89,3.66 U10.13
PHY1_VDD_3V3: length 59.9
  TOP w0.305: C50.1 v1(25.83,11.54) ; v1(22.91,9.89) 22.91,10.27 C226.1 ; C225.1 v1(28.5,11.41)
  TOP w0.381: C224.1 28.63,6.71 v1(28.63,7.22) ; v1(30.53,5.82) 30.79,5.82 R15.1
  TOP w0.508: v1(15.8,12.3) 15.8,12.86 16.07,13.13 E16.2 ; R16.1 v1(8.18,58.27)
  L7_SIGNAL w0.406: v1(8.18,58.27) 8.18,55.99 7.42,55.23 7.42,52.18 8.18,51.42 8.18,15.48 9.07,14.59 10.72,14.59 11.1,14.97 12.63,14.97 15.04,12.55
  BOTTOM w0.305: v1(22.91,9.89) 22.53,9.89 21.89,10.53 U10.36
PS-SRST#: length 72.1
  TOP w0.127: v1(36.34,31.39) U1.B10
  TOP w0.14: R7.2 43.87,7.58 Q5.2 43.87,7.68 v1(43.87,8.74)
  L3_SIGNAL w0.095: v1(36.34,31.39) 36.73,31.78 37.43,31.78 39.59,33.94 39.59,36.7 41.23,38.34 44.63,38.34 44.78,38.18 46.3,38.18 46.45,38.34 52.12,38.34 57.27,43.48 64,43.48 66.35,45.83 v1(68.25,45.83)
  L16_SIGNAL w0.095: v1(43.87,8.74) 39.3,13.32 39.3,20.17 39.59,20.47 39.59,24.83 37.49,26.93 36.32,26.93 35.93,27.32 35.93,28.75 36,28.81 36,29.13 36.19,29.33 36.35,29.33 36.67,29.65 36.67,30.29 36.34,30.63 v1(36.34,31.39)
  BOTTOM w0.14: R19.1 v1(68.25,45.83)
PS_MIO00_500_JX4: length 67.1
  TOP w0.127: U1.E6 v1(33.94,34.59)
  L15_SIGNAL w0.095: v1(33.94,34.59) 33.94,34.55 34.24,34.25 37.41,34.25 39.04,32.62 40.31,32.62 41.26,31.67 49.77,31.67 50.34,31.1 50.34,30.08 51.23,29.19 51.23,27.54 52.95,25.83 53.33,25.83 54.28,24.87 54.28,23.79 58.41,19.67 61.2,19.67 63.23,17.63 66.47,17.63 67.49,18.65 80.38,18.65 83,16.03 83.44,16.03 84.99,14.48 84.99,12.78 v1(84.38,12.17)
  BOTTOM w0.14: v1(84.38,12.17) JX4.97
PS_MIO01_500_QSPI0_SS_B: length 50.2
  TOP w0.127: U1.A7 v1(37.14,33.79)
  TOP w0.14: U13.C2 67.62,57.64 v1(67.11,58.15)
  L3_SIGNAL w0.095: v1(67.11,58.15) 66.07,57.11 66.07,56.86 67.15,55.77 67.15,55.52 66.97,55.35 66.72,55.35 65.64,56.43 65.39,56.43 64.82,55.86 64.82,54.29 62.41,51.87 61.09,51.87 53.9,44.69 42.22,44.69 41.71,44.18 41.71,40.44 38.69,37.42 38.69,35.24 38,34.55 38,34.22 37.57,33.79 v1(37.14,33.79)
  BOTTOM w0.14: R28.2 67.11,58.91 v1(67.11,58.15)
PS_MIO02_500_QSPI0_IO0: length 53
  TOP w0.127: U1.B8 v1(36.34,32.99)
  TOP w0.14: v1(67.12,57.12) U13.D3
  L3_SIGNAL w0.095: v1(67.12,57.12) 67.74,57.75 67.74,58.15 67.99,58.39 68.39,58.39 68.62,58.16 68.62,55.44 68.03,54.85 66.07,54.85 62.64,51.42 61.27,51.42 53.87,44.03 53.11,44.03 49.81,40.72 46,40.72 45.21,39.94 41.76,39.94 38.95,37.13 38.95,34.44 37.9,33.38 36.76,33.38 36.36,32.99 v1(36.34,32.99)
  BOTTOM w0.14: v1(67.12,57.12) 66.12,57.12 65.14,58.1 65.14,58.63 64.73,59.04 R120.1
PS_MIO03_500_QSPI0_IO1: length 52
  TOP w0.127: U1.D6 v1(34.74,34.59)
  TOP w0.14: U13.D2 v1(66.11,58.13)
  L3_SIGNAL w0.095: v1(34.74,34.59) 35.13,34.2 37.31,34.2 38.39,35.27 38.39,37.71 41.38,40.7 41.38,44.81 42.05,45.49 54.14,45.49 60.93,52.28 62,52.28 63.68,53.96 63.68,54.29 63.86,54.47 64.14,54.47 64.31,54.64 64.31,54.89 64.14,55.07 63.86,55.07 63.68,55.25 63.68,55.5 63.86,55.67 64.14,55.67 64.31,55.85 64.31,56.1 64.14,56.28 63.86,56.28 63.68,56.45 63.68,56.75 63.93,57 64.97,57 v1(66.11,58.13)
  BOTTOM w0.14: R119.1 66.6,57.64 v1(66.11,58.13)
PS_MIO04_500_QSPI0_IO2: length 51.3
  TOP w0.127: U1.B7 v1(36.34,33.79)
  TOP w0.14: v1(66.47,49.11) 66.47,53.16 67.11,53.8 67.11,55.12 U13.C4
  L3_SIGNAL w0.095: v1(36.34,33.79) 35.94,33.4 35.94,32.77 36.12,32.6 37.76,32.6 39.3,34.13 39.3,36.96 41.49,39.16 51.42,39.16 54.41,42.15 54.41,43.92 61.39,50.91 64.67,50.91 v1(66.47,49.11)
  BOTTOM w0.14: R121.1 66.35,48.37 66.47,48.5 66.47,49.11 v1(66.47,49.11)
PS_MIO05_500_QSPI0_IO3: length 50.4
  TOP w0.127: U1.A6 v1(37.14,34.59)
  TOP w0.14: U13.D4 66.58,55.62 66.09,56.12 65.33,56.12 64.95,56.5 64.95,56.88 v1(64.31,57.51)
  L3_SIGNAL w0.095: v1(37.14,34.59) 38.1,35.55 38.1,37.95 41,40.85 41,45.3 42.04,46.34 54.33,46.34 60.71,52.71 61.57,52.71 62.23,53.37 62.23,54.12 62.41,54.3 62.89,54.3 63.07,54.48 63.07,54.73 62.89,54.9 62.41,54.9 62.23,55.08 62.23,55.33 62.41,55.51 63.02,55.51 63.2,55.68 63.2,55.93 63.02,56.11 62.41,56.11 62.23,56.29 62.23,57.23 62.51,57.51 v1(64.31,57.51)
  BOTTOM w0.14: R122.1 v1(64.31,57.51)
